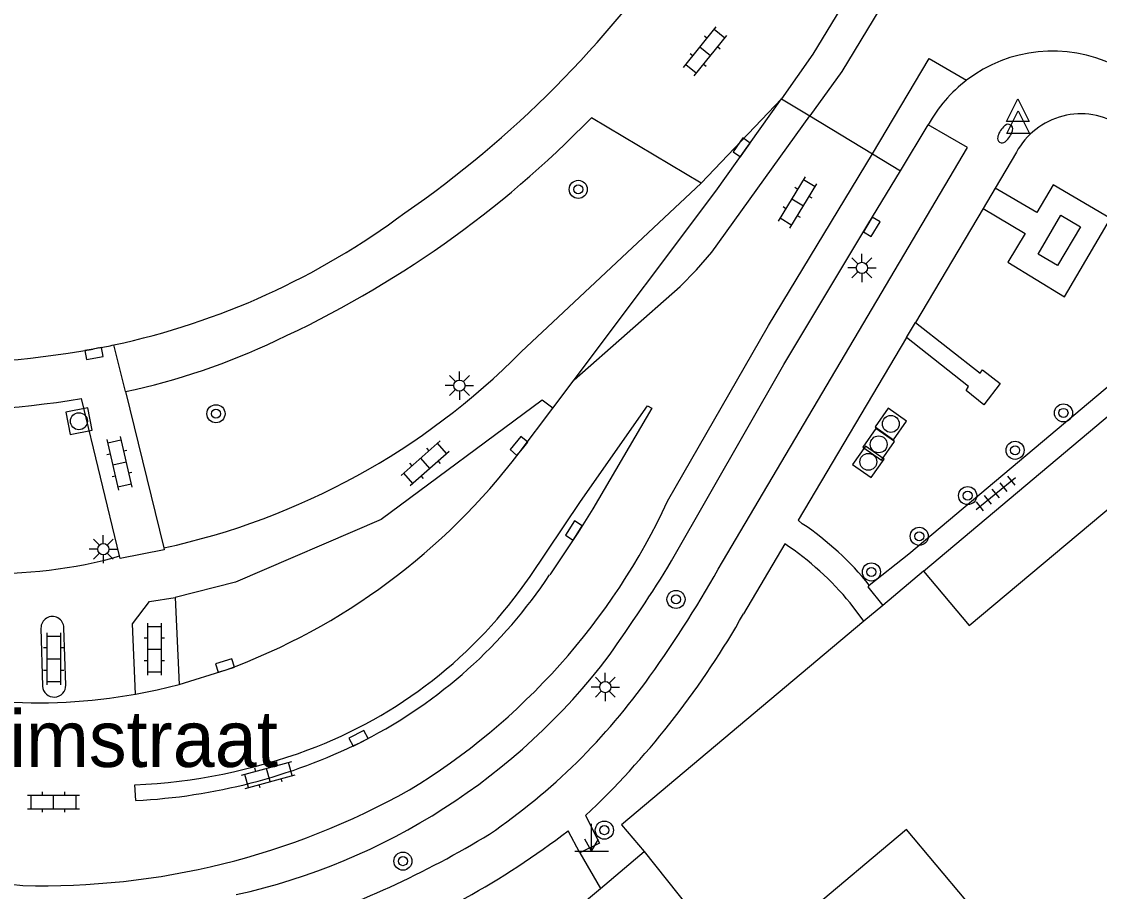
# Model space of a CAD drawing. Extents: x 136000 to 141000, y 400494 to 402006.
# Drawn here: x 137451.6 to 137499.32, y 401791.12 to 401829.62 of the extents above; entities that cross this region are included whole.
import ezdxf

# ---------------------------------------------------------------- set-up
doc = ezdxf.new("R2010")
doc.units = 0
for name, color, linetype in [('gg-afsc-erfafscheiding', 7, 'Continuous'), ('gg-afsc-hekwerk', 7, 'Continuous'), ('gg-anno-openbare ruimte label', 7, 'Continuous'), ('gg-bbg-gedigitaliseerde bebouwing', 7, 'Continuous'), ('gg-bbg-gedigitaliseerde bijgebouw', 7, 'Continuous'), ('gg-bbg-hoofdgebouw', 7, 'Continuous'), ('gg-bbg-lage trafo', 7, 'Continuous'), ('gg-knt-verharding', 7, 'Continuous'), ('gg-knt-verharding nz', 7, 'Continuous'), ('gt-grn-groengrens', 7, 'Continuous'), ('gt-grn-weggrens', 7, 'Continuous'), ('gt-symb-boom', 7, 'Continuous'), ('gt-symb-brandkraan', 7, 'Continuous'), ('gt-symb-klinker verharding', 7, 'Continuous'), ('gt-symb-kolk', 7, 'Continuous'), ('gt-symb-lichtmast', 7, 'Continuous'), ('gt-symb-markant object', 7, 'Continuous'), ('gt-symb-rioolschacht', 7, 'Continuous'), ('gt-symb-tegel verharding', 7, 'Continuous'), ('gt-symb-waterafsluiter', 7, 'Continuous')]:
    doc.layers.add(name, color=color, linetype=linetype)

# ---------------------------------------------------------------- blocks, each defined once
blk = doc.blocks.new('gt0-KL1')
at = {"layer": 'gt-symb-klinker verharding'}
for p, q in [((-1.15, 0.3), (1.15, 0.3)), ((-1, -0.3), (-1, 0.3)), ((-0.5, 0.3), (-0.5, 0.45)), ((0, -0.3), (0, 0.3)), ((0.5, 0.3), (0.5, 0.45)), ((1, -0.3), (1, 0.3)), ((-1.15, -0.3), (1.15, -0.3)), ((-0.5, -0.45), (-0.5, -0.3)), ((0.5, -0.45), (0.5, -0.3))]:
    blk.add_line(p, q, dxfattribs=at)
blk = doc.blocks.new('gt0-KOLK')
at = {"layer": 'gt-symb-kolk'}
blk.add_lwpolyline([(0, 0), (0.375, 0), (0.375, 0.4), (-0.375, 0.4), (-0.375, 0), (0, 0)], dxfattribs=at)
blk = doc.blocks.new('gt0-BR')
at = {"layer": 'gt-symb-brandkraan'}
for centre, radius, start, end in [((-0.244, 0), 0.206, 107.5669, 252.4331), ((0.599, -2.664), 3, 106.892, 107.5669), ((0, -0.691), 0.938, 73.108, 106.892), ((-0.599, -2.664), 3, 72.4331, 73.108), ((0.244, 0), 0.206, 287.567, 72.4331), ((0.599, 2.664), 3, 252.4331, 253.108), ((0, 0.691), 0.938, 253.108, 286.8921), ((-0.599, 2.664), 3, 286.8921, 287.567)]:
    blk.add_arc(centre, radius, start, end, dxfattribs=at)
blk = doc.blocks.new('gt0-WAFSL')
at = {"layer": 'gt-symb-waterafsluiter'}
for p, q in [((-0.5, -0.333), (0, 0.667)), ((0, 0.667), (0.5, -0.333)), ((0.5, -0.333), (-0.5, -0.333))]:
    blk.add_line(p, q, dxfattribs=at)
blk = doc.blocks.new('gt0-BOOM')
at = {"layer": 'gt-symb-boom'}
for radius in [0.4, 0.2]:
    blk.add_circle((0, 0), radius, dxfattribs=at)
blk = doc.blocks.new('gt0-LMAST')
at = {"layer": 'gt-symb-lichtmast'}
for p, q in [((-0.005, 0.246), (-0.005, 0.621)), ((-0.182, 0.173), (-0.447, 0.438)), ((0.172, 0.173), (0.437, 0.438)), ((-0.255, -0.004), (-0.63, -0.004)), ((-0.182, -0.181), (-0.447, -0.446)), ((-0.005, -0.254), (-0.005, -0.629)), ((0.437, -0.446), (0.172, -0.181)), ((0.245, -0.004), (0.62, -0.004))]:
    blk.add_line(p, q, dxfattribs=at)
blk.add_circle((-0.005, -0.004), 0.25, dxfattribs=at)
blk = doc.blocks.new('gt0-TEG1')
at = {"layer": 'gt-symb-tegel verharding'}
for p, q in [((-1.125, 0), (1.125, 0)), ((-0.9, -0.25), (-0.9, 0.25)), ((-0.45, -0.25), (-0.45, 0.25)), ((0, -0.25), (0, 0.25)), ((0.45, -0.25), (0.45, 0.25)), ((0.9, -0.25), (0.9, 0.25))]:
    blk.add_line(p, q, dxfattribs=at)
blk = doc.blocks.new('gt0-RS')
at = {"layer": 'gt-symb-rioolschacht'}
blk.add_lwpolyline([(-0.5, -0.5), (0.5, -0.5), (0.5, 0.5), (-0.5, 0.5)], close=True, dxfattribs=at)
blk.add_circle((0, 0), 0.375, dxfattribs=at)
blk = doc.blocks.new('gt0-MARKOB')
at = {"layer": 'gt-symb-markant object'}
for p, q in [((0, 0), (0, 1.2)), ((0, 0), (-0.3, 0.52)), ((0, 0), (0.3, 0.52)), ((-0.75, 0), (0.75, 0))]:
    blk.add_line(p, q, dxfattribs=at)

msp = doc.modelspace()

# ---------------------------------------------------------------- linework, layer by layer
at = {"layer": 'gg-afsc-erfafscheiding'}
msp.add_lwpolyline([(137479.165, 401792.881), (137481.682, 401789.721), (137487.832, 401783.887)], dxfattribs=at)
at = {"layer": 'gg-afsc-hekwerk'}
for p, q in [((137491.527, 401805.294), (137489.723, 401803.778)), ((137489.723, 401803.778), (137488.893, 401803.081))]:
    msp.add_line(p, q, dxfattribs=at)
msp.add_lwpolyline([(137488.893, 401803.081), (137478.168, 401794.068), (137479.165, 401792.881)], dxfattribs=at)
at = {"layer": 'gg-bbg-gedigitaliseerde bebouwing'}
msp.add_lwpolyline([(137493.553, 401802.883), (137501.113, 401809.22), (137500.825, 401809.565), (137501.545, 401810.168), (137505.203, 401805.804)], dxfattribs=at)
at = {"layer": 'gg-bbg-gedigitaliseerde bijgebouw'}
msp.add_lwpolyline([(137491.926, 401789.505), (137493.397, 401790.738), (137490.782, 401793.858), (137489.308, 401792.623), (137486.14, 401789.967), (137488.755, 401786.847), (137491.926, 401789.505)], dxfattribs=at)
at = {"layer": 'gg-bbg-hoofdgebouw'}
msp.add_line((137491.527, 401805.294), (137493.553, 401802.883), dxfattribs=at)
msp.add_lwpolyline([(137491.527, 401805.294), (137502.62, 401814.616), (137504.194, 401812.744), (137507.813, 401815.819)], dxfattribs=at)
at = {"layer": 'gg-bbg-lage trafo'}
msp.add_lwpolyline([(137496.602, 401819.323), (137497.614, 401821.043), (137498.476, 401820.536), (137497.463, 401818.816), (137496.602, 401819.323)], dxfattribs=at)
at = {"layer": 'gg-knt-verharding'}
for p, q in [((137485.247, 401826.204), (137486.502, 401825.444)), ((137481.695, 401822.471), (137476.829, 401825.362)), ((137486.502, 401825.444), (137489.269, 401823.767)), ((137490.519, 401823.01), (137491.739, 401825.054)), ((137489.269, 401823.767), (137490.519, 401823.01)), ((137495.642, 401823.833), (137494.702, 401822.247)), ((137473.725, 401815.004), (137481.695, 401822.471)), ((137494.169, 401821.349), (137491.176, 401816.3)), ((137455.031, 401815.172), (137454.779, 401815.125)), ((137475.128, 401812.512), (137476.071, 401813.767)), ((137456.205, 401813.244), (137457.898, 401806.324)), ((137455.941, 401805.967), (137454.262, 401812.929)), ((137473.629, 401810.535), (137475.128, 401812.512)), ((137485.399, 401806.499), (137483.563, 401803.406)), ((137455.615, 401805.866), (137455.941, 401805.967)), ((137458.407, 401804.127), (137458.575, 401800.282)), ((137488.893, 401803.081), (137488.285, 401803.886)), ((137452.463, 401802.767), (137452.526, 401800.203)), ((137453.564, 401800.252), (137453.475, 401802.791)), ((137458.575, 401800.282), (137460.667, 401800.928)), ((137466.807, 401797.82), (137466.611, 401797.717)), ((137456.657, 401795.142), (137456.619, 401795.835)), ((137476.316, 401792.828), (137475.794, 401793.802))]:
    msp.add_line(p, q, dxfattribs=at)
for points in [[(137476.071, 401813.767), (137482.342, 401822.114), (137485.247, 401826.204)], [(137482.626, 401805.706), (137493.483, 401824.04), (137491.739, 401825.054)], [(137480.376, 401805.744), (137485.343, 401814.437), (137489.069, 401820.635), (137490.519, 401823.01)], [(137494.169, 401821.349), (137496.032, 401820.242), (137495.264, 401818.975), (137497.779, 401817.428), (137499.815, 401820.901), (137497.274, 401822.384), (137496.542, 401821.163), (137494.702, 401822.247)], [(137489.131, 401804.668), (137490.884, 401806.06), (137501.977, 401815.382), (137503.768, 401815.581), (137510.103, 401820.879)], [(137491.176, 401816.3), (137494.039, 401814.051), (137494.138, 401814.202), (137494.921, 401813.592), (137494.207, 401812.648), (137493.417, 401813.291), (137493.526, 401813.463), (137490.782, 401815.637)], [(137490.782, 401815.637), (137485.989, 401807.552), (137486.164, 401807.394)], [(137475.128, 401812.512), (137474.65, 401812.861), (137467.529, 401807.576), (137461.077, 401804.811), (137458.407, 401804.127)], [(137474.115, 401805.058), (137476.343, 401808.381), (137479.315, 401812.613), (137479.507, 401812.513), (137476.894, 401808.058), (137476.225, 401806.988), (137474.982, 401805.13)], [(137489.131, 401804.668), (137489.072, 401804.602), (137489.723, 401803.778)], [(137456.651, 401799.854), (137457.605, 401800.045), (137458.575, 401800.282)], [(137476.824, 401794.719), (137476.571, 401794.474), (137477.19, 401793.26), (137476.316, 401792.828)]]:
    msp.add_lwpolyline(points, dxfattribs=at)
for centre, radius, start, end in [((137441.836, 401859.904), 47.077, 304.5926, 325.7588), ((137443.598, 401857.604), 46.302, 294.5983, 315.8658), ((137498.496, 401822.287), 3.246, 57.0892, 151.5548), ((137448.769, 401847.655), 33.081, 282.0803, 306.7526), ((137447.192, 401858.121), 43.661, 256.4944, 280.0078), ((137449.583, 401843.534), 28.881, 280.8739, 282.2123), ((137450.145, 401842.08), 29.466, 281.8689, 295.5879), ((137451.219, 401837.271), 31.66, 282.1782, 315.3051), ((137447.15, 401857.066), 44.707, 256.2925, 279.1536), ((137450.717, 401827.9), 28.749, 290.2483, 322.8409), ((137478.941, 401796.555), 13.025, 38.5265, 56.3215), ((137450.284, 401826.641), 21.449, 249.7388, 284.3926), ((137478.021, 401795.45), 13.285, 39.4168, 56.2675), ((137419.111, 401843.192), 71.804, 324.56163, 328.56511), ((137438.019, 401830.449), 51.009, 324.244, 330.9836), ((137457.085, 401816.74), 20.652, 290.3861, 325.5508), ((137456.829, 401817.204), 21.801, 297.2358, 326.3697), ((137452.969, 401802.781), 0.506, 1.1299, 181.5872), ((137450.487, 401822.107), 37.997, 313.8787, 330.5158), ((137454.998, 401818.679), 28.364, 282.4365, 322.8717), ((137456.603, 401816.722), 27.908, 304.2767, 324.8196), ((137452.309, 401824.057), 24.589, 265.7251, 280.171), ((137453.044, 401800.243), 0.52, 184.4437, 0.9617), ((137455.386, 401820.584), 25.473, 272.8609, 296.1469), ((137455.411, 401821.555), 25.749, 272.6895, 290.1461), ((137450.392, 401829.626), 42.124, 287.7632, 301.3718), ((137453.135, 401823.414), 37.287, 290.6907, 307.4237)]:
    msp.add_arc(centre, radius, start, end, dxfattribs=at)
at = {"layer": 'gg-knt-verharding nz'}
for p, q in [((137481.695, 401822.471), (137485.247, 401826.204)), ((137494.702, 401822.247), (137494.169, 401821.349)), ((137490.782, 401815.637), (137491.176, 401816.3))]:
    msp.add_line(p, q, dxfattribs=at)
for points in [[(137498.405, 401844.639), (137497.12, 401842.598), (137487.921, 401827.4), (137486.502, 401825.444)], [(137492.462, 401837.76), (137486.636, 401828.181), (137485.247, 401826.204)], [(137489.269, 401823.767), (137491.786, 401827.98), (137493.437, 401827.026)], [(137476.071, 401813.767), (137480.763, 401817.897), (137481.485, 401818.628), (137482.16, 401819.405), (137486.502, 401825.444)], [(137480.203, 401808.391), (137484.667, 401816.159), (137489.269, 401823.767)], [(137457.898, 401806.324), (137457.915, 401806.237), (137455.963, 401805.856), (137455.941, 401805.967)], [(137456.651, 401799.854), (137456.516, 401802.965), (137457.274, 401803.958), (137458.407, 401804.127)]]:
    msp.add_lwpolyline(points, dxfattribs=at)
for centre, radius, start, end in [((137497.239, 401822.043), 6.268, 64.1638, 127.339), ((137497.402, 401821.895), 6.484, 127.6935, 150.846), ((137453.444, 401820.826), 29.507, 301.2984, 335.0759), ((137455.211, 401826.851), 35.643, 236.5878, 264.2754), ((137452.551, 401824.524), 33.151, 268.4528, 299.2965)]:
    msp.add_arc(centre, radius, start, end, dxfattribs=at)
at = {"layer": 'gt-grn-groengrens'}
for p, q in [((137476.316, 401792.828), (137477.23, 401791.255)), ((137477.23, 401791.255), (137479.165, 401792.881))]:
    msp.add_line(p, q, dxfattribs=at)
msp.add_lwpolyline([(137470.143, 401780.207), (137476.156, 401790.353), (137477.23, 401791.255)], dxfattribs=at)
at = {"layer": 'gt-grn-weggrens'}
msp.add_line((137456.205, 401813.244), (137455.692, 401815.307), dxfattribs=at)

# ---------------------------------------------------------------- block references
at = {"layer": 'gt-symb-boom'}
for p in [(137476.245, 401822.191), (137497.727, 401812.3), (137460.209, 401812.262), (137495.587, 401810.643), (137493.485, 401808.637), (137491.341, 401806.836), (137489.223, 401805.258), (137480.574, 401804.044), (137477.402, 401793.832), (137468.484, 401792.46)]:
    msp.add_blockref('gt0-BOOM', p, dxfattribs=at)
at = {"layer": 'gt-symb-brandkraan', "rotation": -122.74104467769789}
msp.add_blockref('gt0-BR', (137495.145, 401824.658), dxfattribs=at)
at = {"layer": 'gt-symb-klinker verharding'}
for p, rotation in [((137481.867, 401828.296), 51.00900595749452), ((137485.959, 401821.607), 58.66279427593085), ((137455.935, 401810.067), -76.99249520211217), ((137469.471, 401810.067), 41.6335393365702), ((137457.477, 401801.843), -90.00000000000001), ((137453.023, 401801.414), -90.00000000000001), ((137462.532, 401796.274), 15.245070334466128)]:
    msp.add_blockref('gt0-KL1', p, dxfattribs=dict(at, rotation=rotation))
msp.add_blockref('gt0-KL1', (137453.023, 401795.075), dxfattribs=at)
at = {"layer": 'gt-symb-kolk'}
for p, rotation in [((137483.641, 401823.93), 54.76534259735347), ((137489.069, 401820.635), -121.0191120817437), ((137454.779, 401815.125), -169.53996881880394), ((137473.773, 401810.709), 50.41760978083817), ((137476.225, 401806.988), 58.002315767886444), ((137460.667, 401800.928), 17.161465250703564), ((137466.611, 401797.717), 27.73448506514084)]:
    msp.add_blockref('gt0-KOLK', p, dxfattribs=dict(at, rotation=rotation))
at = {"layer": 'gt-symb-lichtmast'}
for p in [(137488.808, 401818.718), (137470.991, 401813.508), (137455.228, 401806.27), (137477.45, 401800.169)]:
    msp.add_blockref('gt0-LMAST', p, dxfattribs=at)
at = {"layer": 'gt-symb-markant object'}
msp.add_blockref('gt0-MARKOB', (137476.84, 401792.909), dxfattribs=at)
at = {"layer": 'gt-symb-rioolschacht'}
for p, rotation in [((137454.143, 401811.929), 11.093101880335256), ((137490.083, 401811.809), 55.112433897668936), ((137489.547, 401810.906), 55.11243389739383), ((137489.088, 401810.132), 55.11243389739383)]:
    msp.add_blockref('gt0-RS', p, dxfattribs=dict(at, rotation=rotation))
at = {"layer": 'gt-symb-tegel verharding', "rotation": 39.196688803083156}
msp.add_blockref('gt0-TEG1', (137494.73, 401808.732), dxfattribs=at)
at = {"layer": 'gt-symb-waterafsluiter'}
for p in [(137495.705, 401825.53), (137495.726, 401824.994)]:
    msp.add_blockref('gt0-WAFSL', p, dxfattribs=at)

# ---------------------------------------------------------------- texts
at = {"layer": 'gg-anno-openbare ruimte label'}
msp.add_text('Slimstraat', height=2.5, dxfattribs=at).set_placement((137448.082, 401796.628))

doc.saveas('drawing.dxf')
